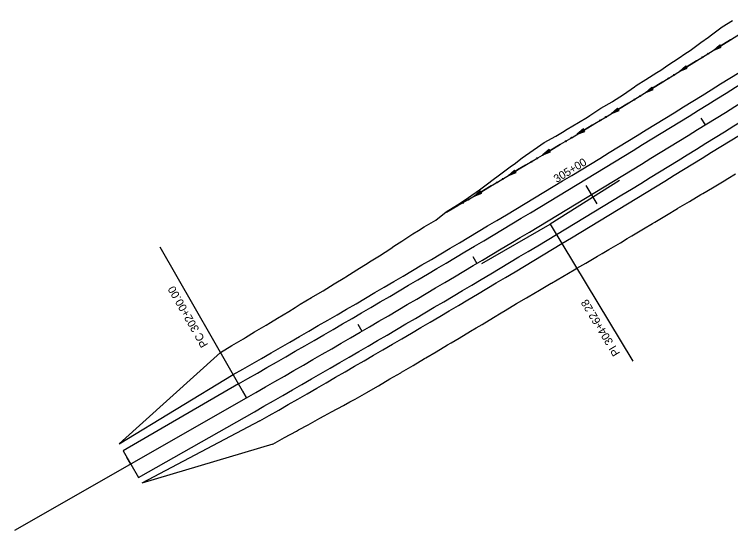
# Model space of a CAD drawing. Extents: x 1375694 to 1433473, y 1931050 to 1967991.
# Drawn here: x 1416684 to 1417220, y 1955303 to 1955690 of the extents above; entities that cross this region are included whole.
import ezdxf

# ---------------------------------------------------------------- set-up
doc = ezdxf.new("R2010")
doc.units = 0
for name, color, linetype in [('62', 7, 'Continuous'), ('R_Horz Alg', 7, 'Continuous'), ('R_Horz Alg Annot', 7, 'Continuous'), ('R_Proposed Const Limits', 7, 'Continuous'), ('R_Proposed Road', 7, 'Continuous')]:
    doc.layers.add(name, color=color, linetype=linetype)

msp = doc.modelspace()

# ---------------------------------------------------------------- linework, layer by layer
at = {"layer": '62'}
for p, q in [((1417212.14, 1955667.14), (1417207.61, 1955663.06)), ((1417207.61, 1955663.06), (1417213.26, 1955665.34)), ((1417213.26, 1955665.34), (1417212.14, 1955667.14)), ((1417186.65, 1955651.25), (1417182.13, 1955647.16)), ((1417182.13, 1955647.16), (1417187.77, 1955649.46)), ((1417187.77, 1955649.46), (1417186.65, 1955651.25)), ((1417161.18, 1955635.32), (1417156.65, 1955631.25)), ((1417156.65, 1955631.25), (1417162.3, 1955633.53)), ((1417162.3, 1955633.53), (1417161.18, 1955635.32)), ((1417135.64, 1955619.54), (1417131.06, 1955615.52)), ((1417131.06, 1955615.52), (1417136.74, 1955617.73)), ((1417136.74, 1955617.73), (1417135.64, 1955619.54)), ((1417109.95, 1955603.97), (1417105.37, 1955599.96)), ((1417105.37, 1955599.96), (1417111.05, 1955602.16)), ((1417111.05, 1955602.16), (1417109.95, 1955603.97)), ((1417084.21, 1955588.51), (1417079.6, 1955584.53)), ((1417079.6, 1955584.53), (1417085.29, 1955586.69)), ((1417085.29, 1955586.69), (1417084.21, 1955588.51)), ((1417058.43, 1955573.09), (1417053.84, 1955569.08)), ((1417053.84, 1955569.08), (1417059.52, 1955571.27)), ((1417059.52, 1955571.27), (1417058.43, 1955573.09)), ((1417032.7, 1955557.59), (1417028.1, 1955553.59)), ((1417033.79, 1955555.78), (1417032.7, 1955557.59)), ((1417028.1, 1955553.59), (1417033.79, 1955555.78))]:
    msp.add_line(p, q, dxfattribs=at)
for points in [[(1417007.38, 1955541.44), (1417015.99, 1955546.45), (1417023.33, 1955550.74), (1417024.59, 1955551.49), (1417033.13, 1955556.62), (1417041.67, 1955561.75), (1417041.99, 1955561.94), (1417050.2, 1955566.89), (1417058.73, 1955572.03), (1417060.63, 1955573.18), (1417067.25, 1955577.19), (1417075.81, 1955582.28), (1417079.31, 1955584.36), (1417084.37, 1955587.38), (1417092.92, 1955592.49), (1417098, 1955595.52), (1417101.47, 1955597.6), (1417110, 1955602.76), (1417116.63, 1955606.79), (1417118.51, 1955607.93), (1417127.03, 1955613.09), (1417135.25, 1955618.07), (1417135.55, 1955618.25), (1417144.05, 1955623.45), (1417152.52, 1955628.68), (1417153.79, 1955629.47), (1417160.98, 1955633.95), (1417169.43, 1955639.23), (1417172.26, 1955640.99), (1417177.88, 1955644.5), (1417186.32, 1955649.79), (1417190.72, 1955652.54), (1417194.77, 1955655.06), (1417203.23, 1955660.33), (1417209.19, 1955664.05), (1417211.68, 1955665.6), (1417220.12, 1955670.89), (1417227.66, 1955675.58)], [(1417220.33, 1955671.01), (1417220.12, 1955670.89), (1417211.68, 1955665.6), (1417209.19, 1955664.05), (1417207.61, 1955663.06)], [(1417194.85, 1955655.11), (1417194.77, 1955655.06), (1417190.72, 1955652.54), (1417186.32, 1955649.79), (1417182.13, 1955647.16)], [(1417194.88, 1955655.13), (1417194.85, 1955655.11)], [(1417169.38, 1955639.19), (1417160.98, 1955633.95), (1417156.65, 1955631.25)], [(1417169.41, 1955639.21), (1417169.38, 1955639.19)], [(1417143.87, 1955623.33), (1417135.55, 1955618.25), (1417135.25, 1955618.07), (1417131.06, 1955615.52)], [(1417143.9, 1955623.35), (1417143.87, 1955623.33)], [(1417118.19, 1955607.74), (1417116.63, 1955606.79), (1417110, 1955602.76), (1417105.37, 1955599.96)], [(1417118.22, 1955607.76), (1417118.19, 1955607.74)], [(1417092.47, 1955592.22), (1417084.37, 1955587.38), (1417079.6, 1955584.53)], [(1417092.51, 1955592.24), (1417092.47, 1955592.22)], [(1417066.67, 1955576.84), (1417060.63, 1955573.18), (1417058.73, 1955572.03), (1417053.84, 1955569.08)], [(1417066.71, 1955576.86), (1417066.67, 1955576.84)], [(1417040.95, 1955561.32), (1417033.13, 1955556.62), (1417028.1, 1955553.59)], [(1417040.99, 1955561.34), (1417040.95, 1955561.32)], [(1417015.14, 1955545.96), (1417007.38, 1955541.44)], [(1417015.18, 1955545.98), (1417015.14, 1955545.96)]]:
    msp.add_lwpolyline(points, dxfattribs=at)
for centre in [(1417203.39, 1955660.38), (1417199.13, 1955657.73), (1417177.91, 1955644.47), (1417173.66, 1955641.82), (1417152.42, 1955628.57), (1417148.16, 1955625.94), (1417126.8, 1955612.9), (1417122.51, 1955610.31), (1417096.8, 1955594.76), (1417101.1, 1955597.34), (1417071.01, 1955579.38), (1417075.31, 1955581.94), (1417045.28, 1955563.88), (1417049.57, 1955566.46), (1417019.5, 1955548.46), (1417023.82, 1955550.99)]:
    msp.add_circle(centre, 0.375, dxfattribs=at)
at = {"layer": 'R_Horz Alg'}
msp.add_line((1416683.85, 1955303.03), (1416857.46, 1955402.32), dxfattribs=at)
msp.add_arc((1411168.28, 1965349.45), 11459.16, 299.767055, 302.3894, dxfattribs=at)
at = {"layer": 'R_Horz Alg Annot'}
for p in [(1417136.96, 1955565.41), (1417033.76, 1955503.15)]:
    msp.add_line(p, (1417085.13, 1955532.54), dxfattribs=at)
for points in [[(1417197.99, 1955612.03), (1417201.14, 1955606.93)], [(1417111.74, 1955561.49), (1417120.05, 1955547.82)], [(1417085.13, 1955532.54), (1417147.08, 1955429.76)], [(1416857.46, 1955402.32), (1416792.92, 1955515.17)], [(1417027.13, 1955508.28), (1417030.2, 1955503.13)], [(1416941.02, 1955457.53), (1416944.05, 1955452.35)], [(1416854.48, 1955407.53), (1416857.46, 1955402.32)], [(1416767.68, 1955357.88), (1416770.66, 1955352.67)]]:
    msp.add_lwpolyline(points, dxfattribs=at)
at = {"layer": 'R_Proposed Const Limits'}
for p, q in [((1416837.96, 1955436.41), (1416762, 1955367.81)), ((1416877.32, 1955367.6), (1416778.95, 1955338.18))]:
    msp.add_line(p, q, dxfattribs=at)
for points in [[(1417007.18, 1955541.79), (1417015.61, 1955547.1), (1417022.76, 1955551.69), (1417023.97, 1955552.52), (1417032.05, 1955558.41), (1417040.12, 1955564.32), (1417040.43, 1955564.55), (1417048.17, 1955570.26), (1417056.19, 1955576.25), (1417057.98, 1955577.59), (1417064.16, 1955582.31), (1417072.32, 1955588.06), (1417075.65, 1955590.41), (1417080.48, 1955593.79), (1417089.27, 1955598.51), (1417094.36, 1955601.51), (1417097.76, 1955603.7), (1417106.26, 1955608.88), (1417112.96, 1955612.81), (1417114.78, 1955614.03), (1417123.15, 1955619.43), (1417131.47, 1955624.24), (1417131.77, 1955624.42), (1417140.1, 1955629.88), (1417148.26, 1955635.61), (1417149.48, 1955636.47), (1417156.63, 1955641.01), (1417165.09, 1955646.25), (1417167.94, 1955647.98), (1417173.35, 1955651.82), (1417181.64, 1955657.33), (1417185.86, 1955660.37), (1417189.94, 1955662.83), (1417197.98, 1955668.76), (1417203.75, 1955672.77), (1417206.07, 1955674.6), (1417214.06, 1955680.58), (1417221.6, 1955685.26)], [(1416877.32, 1955367.6), (1416886.1, 1955372.46), (1416894.89, 1955377.3), (1416896.52, 1955378.19), (1416903.71, 1955382.1), (1416912.51, 1955386.92), (1416915.78, 1955388.7), (1416921.32, 1955391.74), (1416930.12, 1955396.56), (1416935.01, 1955399.25), (1416938.92, 1955401.4), (1416947.65, 1955406.36), (1416954.11, 1955410.04), (1416956.34, 1955411.36), (1416964.98, 1955416.48), (1416973.04, 1955421.11), (1416973.68, 1955421.48), (1416982.3, 1955426.62), (1416990.96, 1955431.69), (1416991.93, 1955432.25), (1416999.61, 1955436.79), (1417008.22, 1955441.94), (1417010.8, 1955443.44), (1417016.88, 1955447.01), (1417025.47, 1955452.21), (1417029.62, 1955454.69), (1417034.08, 1955457.37), (1417042.72, 1955462.47), (1417048.39, 1955466.04), (1417051.27, 1955467.73), (1417059.84, 1955472.96), (1417067.21, 1955477.3), (1417068.47, 1955478.08), (1417077.16, 1955483.1), (1417085.81, 1955488.18), (1417086.15, 1955488.37), (1417094.45, 1955493.29), (1417103.15, 1955498.3), (1417105.09, 1955499.42), (1417111.83, 1955503.34), (1417120.48, 1955508.44), (1417124.02, 1955510.51), (1417129.13, 1955513.52), (1417137.75, 1955518.66), (1417142.86, 1955521.73), (1417146.36, 1955523.82), (1417154.98, 1955528.96), (1417161.71, 1955532.96), (1417163.61, 1955534.09), (1417172.22, 1955539.26), (1417180.52, 1955544.24), (1417180.82, 1955544.42), (1417189.44, 1955549.57), (1417198.07, 1955554.7), (1417199.36, 1955555.47), (1417206.71, 1955559.8), (1417215.35, 1955564.93), (1417218.2, 1955566.71), (1417223.86, 1955570.25)], [(1416837.96, 1955436.41), (1416846.52, 1955441.53), (1416855.16, 1955446.48), (1416856.73, 1955447.47), (1416863.61, 1955451.78), (1416872.25, 1955456.74), (1416875.37, 1955458.73), (1416880.66, 1955462.12), (1416889.26, 1955467.15), (1416893.95, 1955470.1), (1416897.67, 1955472.5), (1416906.3, 1955477.5), (1416912.69, 1955481.19), (1416914.9, 1955482.53), (1416923.32, 1955487.86), (1416931.22, 1955492.64), (1416931.85, 1955493.02), (1416940.29, 1955498.31), (1416948.72, 1955503.65), (1416949.67, 1955504.22), (1416957.18, 1955508.91), (1416965.54, 1955514.35), (1416968.02, 1955515.97), (1416973.92, 1955519.75), (1416982.25, 1955525.24), (1416986.28, 1955527.86), (1416990.66, 1955530.58), (1416999.36, 1955535.45), (1417007.18, 1955541.79)]]:
    msp.add_lwpolyline(points, dxfattribs=at)
at = {"layer": 'R_Proposed Road'}
for p, q in [((1416762, 1955367.81), (1416847.53, 1955419.68)), ((1416851.5, 1955412.74), (1416764.97, 1955362.61)), ((1416776.45, 1955342.54), (1416863.42, 1955391.9)), ((1416867.39, 1955384.96), (1416778.95, 1955338.18)), ((1416764.97, 1955362.61), (1416776.45, 1955342.54))]:
    msp.add_line(p, q, dxfattribs=at)
for radius in [11439.16, 11447.16, 11471.16, 11479.16]:
    msp.add_arc((1411168.28, 1965349.45), radius, 299.767055, 302.3894, dxfattribs=at)

# ---------------------------------------------------------------- texts
at = {"layer": 'R_Horz Alg'}
for p in [(1416857.34, 1955401.67), (1416683.73, 1955302.38)]:
    msp.add_text('+', height=1, rotation=29.7671, dxfattribs=at).set_placement(p)
at = {"layer": 'R_Horz Alg Annot'}
for s, rotation, p in [('305+00', 31.2671, (1417089.95, 1955563.38)), ('PC 302+00.00', 119.7671, (1416828.94, 1955442.12)), ('PI 304+62.28', 121.0782, (1417137.63, 1955435.74))]:
    msp.add_text(s, height=6, rotation=rotation, dxfattribs=at).set_placement(p)

doc.saveas('drawing.dxf')
